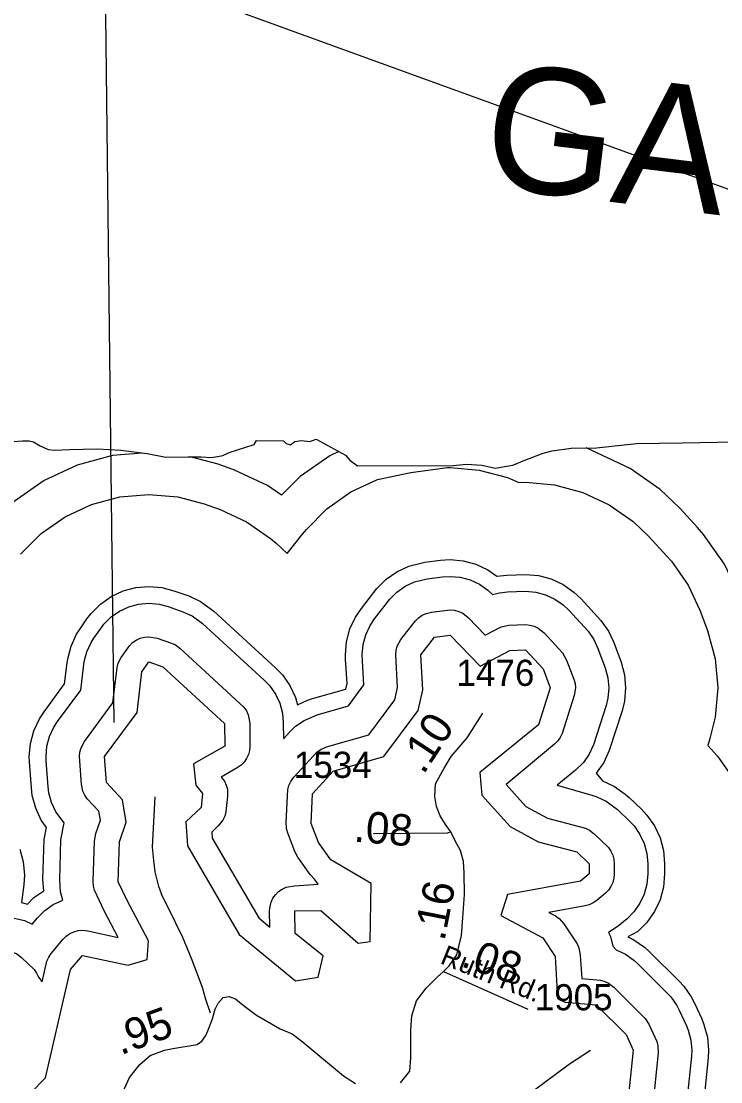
# Model space of a CAD drawing. Extents: x 2290615 to 2522933, y 819489 to 1012715.
# Drawn here: x 2342811 to 2346153, y 1000291 to 1005356 of the extents above; entities that cross this region are included whole.
import ezdxf

# ---------------------------------------------------------------- set-up
doc = ezdxf.new("R2010")
doc.units = 0
for name, color, linetype in [('Exist Boundary Political CountyLine', 7, 'Continuous'), ('Exist Hydrographic Buffer Line', 7, 'Continuous'), ('Exist Hydrographic Lake Shore', 7, 'Continuous'), ('Exist Hydrographic Lake Shore Label', 7, 'Continuous'), ('Exist Road Non-System Type 51', 7, 'Continuous'), ('Exist Road Secondary Mileage Tenths English Label', 7, 'Continuous'), ('Exist Road Secondary Type 51 Attributed', 7, 'Continuous'), ('Exist Road Secondary Type 51 Label', 7, 'Continuous'), ('Exist Road Secondary Type 51 Number Label', 7, 'Continuous'), ('Map Preparation Inset Cut Line', 7, 'Continuous'), ('Map Preparation Longitude Latitude Lines', 7, 'Continuous')]:
    doc.layers.add(name, color=color, linetype=linetype)

msp = doc.modelspace()

# ---------------------------------------------------------------- linework, layer by layer
at = {"layer": 'Exist Boundary Political CountyLine'}
msp.add_lwpolyline([(2342772, 1003349.1), (2342817.8, 1003351.7), (2342850, 1003352), (2342869.9, 1003346.3), (2342902.2, 1003328.6), (2342940.3, 1003311.1), (2342970.3, 1003307.4), (2343042.4, 1003310.4), (2343176.2, 1003313.9), (2343286.5, 1003307.3), (2343412.5, 1003290.5), (2343502.5, 1003273.9), (2343608.5, 1003274.9), (2343670.5, 1003275.9), (2343718.6, 1003272.3), (2343748.6, 1003276.8), (2343774.4, 1003281.1), (2343804.3, 1003295.5), (2343923.8, 1003334.9), (2343935.5, 1003352.8), (2344063.6, 1003352.5), (2344077.6, 1003338.6), (2344097.9, 1003332.9), (2344117.6, 1003349.1), (2344149.6, 1003353.4), (2344189.5, 1003347.8), (2344219.5, 1003360.2), (2344360.2, 1003283.9), (2344380.6, 1003260.1), (2344416.8, 1003232.8), (2344874.7, 1003234.2), (2344938.8, 1003240.8), (2345010.9, 1003235.9), (2345076.8, 1003220.6), (2345118.8, 1003229.2), (2345158.9, 1003235.4), (2345216.3, 1003260.1), (2345303.9, 1003293.3), (2345347.8, 1003304), (2345437.9, 1003316.9), (2345559.6, 1003318.3), (2345749.5, 1003338.6), (2345969.3, 1003341.4), (2346219.3, 1003346.4)], dxfattribs=at)
at = {"layer": 'Exist Hydrographic Buffer Line'}
for points in [[(2344328.9, 1003300.9), (2344285.8, 1003280.8), (2344143.1, 1003180.8), (2344054.3, 1003092.1), (2343987.9, 1003138.8), (2343830, 1003212.4), (2343751.9, 1003239.9), (2343617.7, 1003275)], [(2346602.9, 1000944.5), (2346566, 1001015.8), (2346506.5, 1001100.8), (2346524, 1001283.3), (2346524, 1001332.3), (2346508.8, 1001506), (2346463.7, 1001674.3), (2346389.9, 1001832.3), (2346309.9, 1001946.4), (2346322.6, 1001998.1), (2346338, 1002171.8), (2346322.6, 1002345.3), (2346277.7, 1002513.8), (2346240, 1002614), (2346169.8, 1002762.3), (2346070, 1002905), (2346040.9, 1002938.2), (2345957, 1003029.8), (2345862.7, 1003119.9), (2345720, 1003219.8), (2345510, 1003317.7)], [(2343389.7, 1003293.5), (2343247.2, 1003281.1), (2343078.9, 1003235.9), (2342920.8, 1003162.3), (2342778.1, 1003062.3), (2342654.8, 1002939.1), (2342599.9, 1002867.3), (2342579.2, 1002837.4)], [(2342808.2, 1002810.5), (2342906.6, 1002909), (2343020.9, 1002989), (2343147.4, 1003047.9), (2343281.9, 1003084.1), (2343420.9, 1003096.2), (2343559.9, 1003084.1), (2343685.6, 1003051.1), (2343761.3, 1003024.5), (2343887.8, 1002965.5), (2344002.2, 1002885.5), (2344028.5, 1002862.6), (2344081.6, 1002813.8), (2344154.6, 1002906.2), (2344173.3, 1002929), (2344271.7, 1003027.6), (2344385.9, 1003107.6), (2344512.4, 1003166.6), (2344671.8, 1003200.3), (2344847.1, 1003223.6)], [(2344847.1, 1003223.6), (2344860, 1003224.4), (2344999, 1003212.3), (2345133.5, 1003176.2), (2345187.9, 1003153.2), (2345219.8, 1003153.9), (2345358.9, 1003141.7), (2345493.4, 1003105.6), (2345619.9, 1003046.6), (2345734.1, 1002966.6), (2345809.4, 1002894.7), (2345893.4, 1002803.1), (2345916.6, 1002776.5), (2345996.6, 1002662.2), (2346053, 1002543.6), (2346089.7, 1002445.4), (2346125.8, 1002310.7), (2346137.9, 1002171.8), (2346125.8, 1002032.8), (2346100.5, 1001929.6), (2346089.9, 1001896.6), (2346136.6, 1001846.5), (2346216.8, 1001732.3)], [(2342841.9, 1001139.5), (2342872.4, 1001170.2), (2342918.7, 1001202.6), (2342915.3, 1001257.5), (2342921.2, 1001448.2), (2342931.5, 1001505.1), (2342907.3, 1001540), (2342880.6, 1001596.8), (2342864.4, 1001657.5), (2342859.9, 1001694), (2342850.9, 1001818.2), (2342849.9, 1001844.3), (2342855.4, 1001906.7), (2342871.6, 1001967.4), (2342898.2, 1002024.2), (2342920.4, 1002058.1), (2343018.6, 1002191.2), (2343030.5, 1002291), (2343033.4, 1002311.3), (2343049.6, 1002371.9), (2343076.2, 1002428.8), (2343092.4, 1002454.3), (2343125.4, 1002501.8), (2343145.1, 1002527.6), (2343189.4, 1002572), (2343240.9, 1002608), (2343297.7, 1002634.6), (2343358.4, 1002650.8), (2343420.9, 1002656.2), (2343483.5, 1002650.8), (2343540.3, 1002635.9), (2343611.2, 1002611.1), (2343668, 1002584.5), (2343731.2, 1002538.2), (2344026.2, 1002267.9), (2344058.6, 1002233.9), (2344094.7, 1002182.5), (2344121.2, 1002125.6), (2344130.6, 1002090.2), (2344178.6, 1002112.7), (2344203, 1002120.5), (2344361.1, 1002165.8), (2344367.4, 1002193.4), (2344360.7, 1002308.5), (2344359.9, 1002330), (2344365.4, 1002392.5), (2344381.6, 1002453.1), (2344408.2, 1002510), (2344435.9, 1002551), (2344510.2, 1002646.1), (2344554.4, 1002690.5), (2344605.9, 1002726.5), (2344662.7, 1002753.1), (2344739.4, 1002771.8), (2344813.4, 1002781.5), (2344860, 1002784.5), (2344922.5, 1002778.9), (2344983.2, 1002762.7), (2345040, 1002736.2), (2345083.7, 1002705.5), (2345130.4, 1002710.5), (2345219.8, 1002713.8), (2345282.4, 1002708.3), (2345343.1, 1002692.1), (2345399.9, 1002665.5), (2345451.3, 1002629.5), (2345485.2, 1002597.1), (2345579.7, 1002493.6), (2345615.6, 1002442.2), (2345641, 1002388.9), (2345676.3, 1002294.9), (2345692.5, 1002234.2), (2345698, 1002171.8), (2345692.5, 1002109.2), (2345681, 1002062.8), (2345620.1, 1001872.3), (2345593.7, 1001815.4), (2345557.8, 1001764), (2345588.1, 1001727.3), (2345644.9, 1001700.8), (2345696.4, 1001664.8), (2345714.4, 1001648.6), (2345773.5, 1001592), (2345799.7, 1001563.7), (2345835.6, 1001512.3), (2345862.3, 1001455.4), (2345878.5, 1001394.8), (2345884, 1001332.3), (2345884, 1001283.3), (2345878.5, 1001220.7), (2345862.3, 1001160.1), (2345835.8, 1001103.2), (2345799.7, 1001051.9), (2345756.3, 1001008.2), (2345708.3, 1000982.7), (2345737, 1000969.2), (2345788.5, 1000933.2), (2345810.4, 1000913.1), (2345953.5, 1000771.5), (2345975.7, 1000747.1)], [(2342863.2, 1001043.2), (2342889.4, 1001074.4), (2342923.9, 1001109), (2342963.9, 1001137), (2343009.8, 1001158), (2342999.1, 1001197.7), (2342995.2, 1001255.1), (2343001.2, 1001445.7), (2343016.1, 1001527.7), (2342976.4, 1001580), (2342955.9, 1001624.2), (2342943.1, 1001671.3), (2342939.7, 1001699.7), (2342930.6, 1001824.1), (2342930, 1001844.3), (2342934.1, 1001892.9), (2342946.8, 1001940), (2342967.3, 1001984.2), (2342984.8, 1002010.6), (2343095.7, 1002160.8), (2343112.1, 1002297.5), (2343124.8, 1002344.5), (2343145.3, 1002388.8), (2343158.2, 1002408.7), (2343191.3, 1002456.1), (2343206.4, 1002476.3), (2343240.9, 1002510.7), (2343280.9, 1002538.7), (2343325.2, 1002559.3), (2343372.3, 1002572), (2343420.9, 1002576.2), (2343469.5, 1002572), (2343513.6, 1002560.4), (2343583.7, 1002535.8), (2343627.8, 1002515.2), (2343677.2, 1002479.1), (2343972.1, 1002208.9), (2343997.5, 1002182.5), (2344025.4, 1002142.4), (2344045.9, 1002098.2), (2344058.6, 1002051.1), (2344062.9, 1002005), (2344063.8, 1001928.6), (2344094.5, 1001962.5), (2344122, 1001989), (2344162, 1002016.9), (2344224.9, 1002043.6), (2344375, 1002086.6), (2344448, 1002186.6), (2344440, 1002330), (2344444.1, 1002378.7), (2344456.8, 1002425.7), (2344477.3, 1002470), (2344498.9, 1002501.9), (2344571.5, 1002594.8), (2344605.9, 1002629.3), (2344645.9, 1002657.3), (2344690.2, 1002677.9), (2344749.9, 1002692.5), (2344823.9, 1002702.1), (2344860, 1002704.4), (2344908.4, 1002700.2), (2344955.7, 1002687.6), (2345000, 1002667), (2345040, 1002639), (2345062.8, 1002617.5), (2345096.4, 1002626.6), (2345133.7, 1002630.6), (2345219.8, 1002633.8), (2345268.4, 1002629.5), (2345315.6, 1002616.9), (2345359.9, 1002596.3), (2345399.9, 1002568.3), (2345426.1, 1002543.1), (2345518.4, 1002442.2), (2345546.5, 1002402.2), (2345566, 1002360.7), (2345601, 1002267.5), (2345613.7, 1002220.4), (2345617.8, 1002171.8), (2345613.7, 1002123.2), (2345604.7, 1002087), (2345544.8, 1001899.7), (2345524.3, 1001855.5), (2345496.5, 1001815.4), (2345458.9, 1001778.4), (2345371.2, 1001706.9), (2345536, 1001659.8), (2345560.6, 1001652.2), (2345604.9, 1001631.4), (2345658.9, 1001590.9), (2345717.9, 1001534.3), (2345738.4, 1001512.3), (2345766.5, 1001472.3), (2345787, 1001428), (2345799.7, 1001380.9), (2345804, 1001332.3), (2345804, 1001283.3), (2345799.7, 1001234.6), (2345787, 1001187.5)], [(2344725.9, 1002518.7), (2344744.9, 1002527.5), (2344770.4, 1002533.8), (2344860, 1002544.4), (2344880.7, 1002542.6), (2344901, 1002537.2), (2344919.9, 1002528.3), (2344946.1, 1002507.9), (2345027.1, 1002424.3), (2345104, 1002463.5), (2345140.3, 1002470.7), (2345219.8, 1002473.8), (2345240.8, 1002472), (2345260.9, 1002466.5), (2345279.9, 1002457.7), (2345308.4, 1002434.9), (2345396, 1002339.4), (2345416.3, 1002304.4), (2345450.7, 1002212.8), (2345456.3, 1002192.6), (2345457.9, 1002171.8), (2345452.2, 1002135.5), (2345394.8, 1001954.4), (2345385.9, 1001935.4), (2345374, 1001918.3), (2345357.6, 1001902.4), (2345127.2, 1001710), (2345221.9, 1001606.1), (2345325.6, 1001549.6), (2345505.9, 1001501.7), (2345525, 1001492.9), (2345548.1, 1001475.5), (2345616, 1001409.4), (2345627.9, 1001392.3), (2345636.7, 1001373.4), (2345642.2, 1001353.1), (2345643.9, 1001332.3), (2345643.9, 1001283.3), (2345642.2, 1001262.5), (2345636.7, 1001242.2), (2345627.9, 1001223.2), (2345616, 1001206.1), (2345601.4, 1001191.5), (2345560.2, 1001156.6), (2345543, 1001144.7), (2345523.9, 1001135.8), (2345504.5, 1001130.5), (2345332, 1001099), (2345363, 1001082.5), (2345380.2, 1001070.5), (2345403.2, 1001044.7), (2345465.9, 1000949.1), (2345474.7, 1000930.2), (2345481.7, 1000895.7), (2345488.1, 1000784.1), (2345577.7, 1000775.7), (2345598, 1000770.2), (2345617, 1000761.4), (2345641.4, 1000742.7), (2345791.9, 1000592.9), (2345809, 1000565.7), (2345846.7, 1000482.6), (2345852.2, 1000462.4), (2345853.2, 1000429.2), (2345827.4, 1000179)], [(2342911.2, 1000768), (2342934.1, 1000867.5), (2342942.9, 1000886.5), (2342955, 1000903.5), (2343012, 1000971.6), (2343026.6, 1000986.4), (2343044, 1000998.3), (2343062.9, 1001007.2), (2343083.2, 1001012.6), (2343103.9, 1001014.4), (2343129.1, 1001011.8), (2343275.1, 1000980.4), (2343209.7, 1001104.5), (2343162.1, 1001205.2), (2343156.6, 1001225.4), (2343155, 1001250), (2343160.9, 1001440.6), (2343167.5, 1001475.8), (2343189.6, 1001540.4), (2343182.4, 1001582.5), (2343126.9, 1001642.8), (2343115, 1001659.9), (2343106.2, 1001678.9), (2343099.2, 1001711.3), (2343090, 1001844.3), (2343091.6, 1001865.1), (2343097.1, 1001885.3), (2343113.3, 1001915.5), (2343249.5, 1002099.9), (2343269.6, 1002269.6), (2343275.1, 1002289.9), (2343289.5, 1002317.2), (2343328.9, 1002373.3), (2343343.6, 1002388.2), (2343360.8, 1002400.2), (2343379.9, 1002409), (2343400.2, 1002414.4), (2343420.9, 1002416.2), (2343460.7, 1002409.5), (2343529, 1002385.5), (2343547.8, 1002376.7), (2343569, 1002361.2), (2343874.9, 1002079.6), (2343887, 1002062.5), (2343895.6, 1002043.5), (2343903, 1002003.6), (2343904, 1001894.2), (2343902.2, 1001873.4), (2343896.6, 1001853.1), (2343888, 1001834.2), (2343875.9, 1001817.1), (2343861.2, 1001802.3), (2343843.5, 1001790), (2343766.2, 1001745.9), (2343782, 1001726.7), (2343790.6, 1001707.8), (2343796.2, 1001687.5), (2343797.2, 1001654), (2343789.2, 1001579.9), (2343783.7, 1001559.7), (2343774.8, 1001540.7), (2343752.7, 1001512.8), (2343721.1, 1001483.5), (2343723.4, 1001454.2), (2343945.6, 1001073.2), (2343999.4, 1001029), (2343997.9, 1001106.9), (2343999.8, 1001127.7), (2344005.1, 1001148), (2344013.9, 1001167), (2344026, 1001184.1), (2344040.8, 1001198.9), (2344058, 1001210.9), (2344076.9, 1001219.7), (2344116.3, 1001227), (2344229.9, 1001235.1), (2344212.6, 1001258.6), (2344192.1, 1001280.8), (2344133.3, 1001363.6), (2344118.9, 1001390), (2344083.2, 1001482.7), (2344077.7, 1001503), (2344076.3, 1001529.7), (2344084.7, 1001686.1), (2344090.2, 1001706.4), (2344099, 1001725.3), (2344114, 1001745.9), (2344224.7, 1001866.3), (2344241.9, 1001878.3), (2344269, 1001889.8), (2344471, 1001947.6), (2344595.7, 1002115.1), (2344609.2, 1002173.1), (2344600, 1002330), (2344601.6, 1002350.8), (2344607.1, 1002371.1), (2344625.2, 1002403.7), (2344693.9, 1002491.9), (2344708.6, 1002506.7), (2344725.9, 1002518.7)], [(2342805.1, 1001401.7), (2342821.3, 1001341.1), (2342826.9, 1001278.6), (2342824, 1001231.4), (2342812.7, 1001146.8), (2342841.9, 1001139.5)], [(2345787, 1001187.5), (2345766.5, 1001143.2), (2345738.4, 1001103.2), (2345704.8, 1001069.3), (2345663, 1001034.1), (2345616.4, 1001003.1), (2345625, 1000984.8), (2345637.7, 1000937.8), (2345652.7, 1000920.6), (2345697, 1000900), (2345737, 1000871.9), (2345754, 1000856.3), (2345896.9, 1000714.6), (2345914.6, 1000695.7), (2345942.4, 1000655.7), (2345954.5, 1000632.4), (2345988.4, 1000558.3), (2345997, 1000537.4), (2346009.7, 1000490.2), (2346014, 1000441.6), (2346012.6, 1000412.7), (2345992.1, 1000215.4)], [(2342723.7, 1001084.7), (2342826.7, 1001060.2), (2342863.2, 1001043.2)], [(2342590.9, 1000967.5), (2342771.9, 1000909.9), (2342791, 1000901), (2342813.1, 1000884.3), (2342873, 1000827), (2342884.9, 1000809.9), (2342893.7, 1000790.9), (2342911.2, 1000768)], [(2345975.7, 1000747.1), (2346011.8, 1000695.7), (2346027.1, 1000665.8), (2346061.2, 1000591.6), (2346072.2, 1000564.8), (2346088.4, 1000504.1), (2346094, 1000441.6), (2346091.9, 1000404.4), (2346074.3, 1000233.6)]]:
    msp.add_lwpolyline(points, dxfattribs=at)
at = {"layer": 'Exist Hydrographic Lake Shore'}
for points in [[(2344119.9, 1000998.8), (2344117.9, 1001106.9), (2344243, 1001108.9), (2344419.9, 1000952), (2344478, 1000960.9), (2344482.9, 1001236.9), (2344289.9, 1001350.4), (2344230.9, 1001433.3), (2344196, 1001523.8), (2344203, 1001665.3), (2344302, 1001774.4), (2344543, 1001843.4), (2344707, 1002063.5), (2344730, 1002162.9), (2344719.9, 1002330), (2344786, 1002414.8), (2344860, 1002424.4), (2345003.9, 1002276), (2345145, 1002350.8), (2345219.8, 1002353.8), (2345303.9, 1002262.3), (2345338, 1002171.8), (2345282, 1001995.4), (2345001.9, 1001767.2), (2345010.9, 1001659.2), (2345147, 1001510.5), (2345280.9, 1001437.3), (2345464.9, 1001389), (2345523.9, 1001332.3), (2345523.9, 1001283.3), (2345482.9, 1001248.6), (2345133.9, 1001184.9), (2345101.9, 1001085.2), (2345302.9, 1000978.6), (2345361.9, 1000889.1), (2345373, 1000689.2), (2345407.1, 1000671), (2345556.9, 1000657.4), (2345700.1, 1000515.8), (2345733.9, 1000441.6), (2345707, 1000181.4)], [(2342854, 1000234.2), (2342928, 1000309.5), (2343046.9, 1000826.4), (2343103.9, 1000894.5), (2343321.9, 1000847.7), (2343412.9, 1000874.4), (2343419.9, 1000963.3), (2343318, 1001156), (2343274.9, 1001246.3), (2343280.9, 1001436.9), (2343312.9, 1001530.3), (2343295, 1001637.7), (2343218.9, 1001719.9), (2343209.9, 1001844.3), (2343364.9, 1002054.3), (2343387.9, 1002248.8), (2343420.9, 1002296.2), (2343488, 1002272.7), (2343782.8, 1002002.5), (2343783.9, 1001894.2), (2343635, 1001809.3), (2343644.8, 1001707.9), (2343677.9, 1001666.7), (2343670.9, 1001600.7), (2343596.9, 1001532), (2343605.9, 1001417.5), (2343853, 1000994.2), (2344122, 1000772.3), (2344230.1, 1000789.9), (2344254, 1000892.7), (2344119.9, 1000998.8)]]:
    msp.add_lwpolyline(points, dxfattribs=at)
at = {"layer": 'Exist Road Non-System Type 51'}
msp.add_lwpolyline([(2343716, 1000619.1), (2343693.9, 1000683.1), (2343677.8, 1000741.3), (2343627.8, 1000872.1), (2343583.2, 1000980.5), (2343515.4, 1001119.7), (2343486.4, 1001176.3), (2343468.3, 1001222.7), (2343451, 1001293.5), (2343445.4, 1001347.8), (2343439.2, 1001411.3), (2343451.7, 1001651)], dxfattribs=at)
at = {"layer": 'Exist Road Secondary Type 51 Attributed'}
msp.add_line((2344827.9, 1000816.8), (2345230.3, 1000636.9), dxfattribs=at)
for points in [[(2344863.7, 1001483.8), (2344837.4, 1001520.2), (2344812.1, 1001561.5), (2344794.3, 1001604.6), (2344786.8, 1001652.4), (2344789.6, 1001713.4), (2344831.8, 1001788.4), (2344865.5, 1001844.6), (2344941.5, 1001933.7), (2345015.6, 1002050.9)], [(2344863.7, 1001483.8), (2344846.4, 1001478.4), (2344494.2, 1001474.3)], [(2344827.9, 1000816.8), (2344855.9, 1000843.8), (2344891.8, 1000896.8), (2344913.5, 1000989.8), (2344921.2, 1001073.6), (2344929, 1001185.2), (2344927.4, 1001289.1), (2344924.3, 1001342.6), (2344908.8, 1001395.3), (2344886.2, 1001437.7), (2344863.7, 1001483.8)], [(2344622.8, 1000284.9), (2344667.8, 1000340.8), (2344672.4, 1000404.3), (2344672.4, 1000477.2), (2344672.4, 1000537.7), (2344677.1, 1000605.9), (2344699.7, 1000676.6), (2344745.5, 1000738.1), (2344798.5, 1000789.8), (2344827.9, 1000816.8)], [(2343264.7, 1000170.6), (2343328.9, 1000311.3), (2343378.2, 1000373.8), (2343427.6, 1000416.4), (2343495.3, 1000441.2), (2343535.1, 1000449.7), (2343651, 1000469), (2343674.7, 1000485.4), (2343692.5, 1000511.6), (2343702.2, 1000533.8), (2343724.5, 1000590.6), (2343737.7, 1000636.9), (2343752.5, 1000665.9), (2343775.8, 1000693.6), (2343804.5, 1000698), (2343834.2, 1000686.2), (2343871.3, 1000655.8), (2343935.1, 1000608.9), (2344048.2, 1000543), (2344106.2, 1000519.8), (2344151.1, 1000485), (2344350.1, 1000319.1), (2344408.3, 1000282.8)], [(2344599.1, 998858.3), (2344710.5, 999113.6), (2344780.2, 999282.6), (2344829.8, 999428.4), (2344877.9, 999557.1), (2344962.9, 999783.9), (2345000, 999883.1), (2345030.7, 999992.8), (2345061.7, 1000075), (2345120.6, 1000141.7), (2345257, 1000247.1), (2345430.6, 1000375.8), (2345529.7, 1000440.9)]]:
    msp.add_lwpolyline(points, dxfattribs=at)
at = {"layer": 'Map Preparation Inset Cut Line'}
msp.add_lwpolyline([(2356768.7, 983323.8), (2328294.4, 983323.8), (2321803.3, 997760.3), (2321797.8, 1007474.2), (2338139.7, 1007474.2), (2356768.7, 1000715)], close=True, dxfattribs=at)
at = {"layer": 'Map Preparation Longitude Latitude Lines'}
msp.add_lwpolyline([(2343255, 1002006.4), (2343247.2, 1002669.6), (2343129.1, 1012715.2)], dxfattribs=at)

# ---------------------------------------------------------------- texts
at = {"layer": 'Exist Hydrographic Lake Shore Label'}
msp.add_text('GASTON', height=600, rotation=353, dxfattribs=at).set_placement((2344999.1, 1004570))
at = {"layer": 'Exist Road Secondary Mileage Tenths English Label'}
for s, rotation, p in [('.10', 56.6961, (2344732.2, 1001753.7)), ('.08', 355.1659, (2344396.7, 1001438.1)), ('.16', 78.9304, (2344832.3, 1000959)), ('.08', 340.8674, (2344905.7, 1000844.2)), ('.95', 20.1388, (2343286.1, 1000417))]:
    msp.add_text(s, height=150, rotation=rotation, dxfattribs=at).set_placement(p)
at = {"layer": 'Exist Road Secondary Type 51 Label'}
msp.add_text('Ruth Rd.', height=95, rotation=337.8356, dxfattribs=at).set_placement((2344807.6, 1000858.1))
at = {"layer": 'Exist Road Secondary Type 51 Number Label'}
for s, p in [('1476', (2344890.1, 1002181.4)), ('1534', (2344113.3, 1001742)), ('1905', (2345264.1, 1000631.9))]:
    msp.add_text(s, height=125, dxfattribs=at).set_placement(p)

doc.saveas('drawing.dxf')
